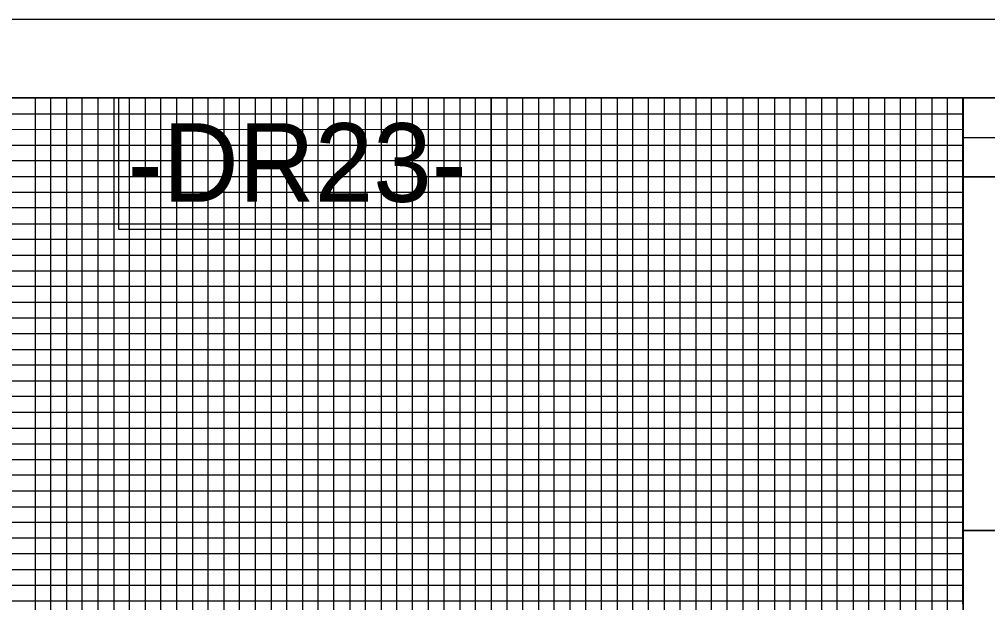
# Model space of a CAD drawing. Extents: x 505602 to 527661, y 418813 to 494436.
# Drawn here: x 506769.1 to 507076.9, y 484023.2 to 484208.7 of the extents above; entities that cross this region are included whole.
import ezdxf

# ---------------------------------------------------------------- set-up
doc = ezdxf.new("R2010")
doc.units = 0
for name, color, linetype in [('Old_Level_1', 7, 'Continuous'), ('Prop Grid Mask', 7, 'Continuous'), ('Sheet Layout Profile Border Port 2', 7, 'Continuous'), ('Sheet Plot Border Outside CELL', 7, 'Continuous'), ('Sheet Profile CELL', 7, 'Continuous'), ('Sheet Profile Grid Major CELL', 7, 'Continuous'), ('Sheet Profile Grid Middle CELL', 7, 'Continuous'), ('Sheet Profile Grid Minor CELL', 7, 'Continuous'), ('Sheet Sticker Exception Certification CELL', 7, 'Continuous')]:
    doc.layers.add(name, color=color, linetype=linetype)

msp = doc.modelspace()

# ---------------------------------------------------------------- linework, layer by layer
at = {"layer": 'Prop Grid Mask'}
msp.add_lwpolyline([(506919.08, 484183.71), (506800.61, 484183.71), (506800.61, 484142), (506919.08, 484142)], close=True, dxfattribs=at)
at = {"layer": 'Sheet Layout Profile Border Port 2'}
msp.add_lwpolyline([(506719.08, 484183.71), (507069.08, 484183.71), (507069.08, 483683.71), (506719.08, 483683.71)], close=True, dxfattribs=at)
at = {"layer": 'Sheet Plot Border Outside CELL'}
msp.add_lwpolyline([(505602.08, 483108.71), (507286.08, 483108.71), (507286.08, 484208.71), (505602.08, 484208.71)], close=True, dxfattribs=at)
at = {"layer": 'Sheet Profile CELL'}
msp.add_line((507069.03, 484171.16), (507269.08, 484171.16), dxfattribs=at)
for points in [[(507269.08, 484183.71), (505769.08, 484183.71), (505769.08, 483133.71), (507269.08, 483133.71)], [(507069.03, 484183.71), (507269.08, 484183.71), (507269.08, 484158.66), (507069.03, 484158.66)], [(507069.03, 484158.66), (507169.08, 484158.66), (507169.08, 484046.16), (507069.03, 484046.16)]]:
    msp.add_lwpolyline(points, close=True, dxfattribs=at)
at = {"layer": 'Sheet Profile Grid Major CELL'}
for points in [[(506769.08, 484183.71), (506819.08, 484183.71), (506819.08, 483683.71), (506869.08, 483683.71), (506869.08, 484183.71), (506919.08, 484183.71), (506919.08, 483683.71), (506969.08, 483683.71), (506969.08, 484183.71), (507019.08, 484183.71), (507019.08, 483683.71), (507069.08, 483683.71), (507069.08, 484183.71), (507095.38, 484183.71)], [(505769.08, 484133.71), (507069.08, 484133.71)], [(507069.08, 484083.71), (505769.08, 484083.71), (505769.08, 484033.71), (507069.08, 484033.71)]]:
    msp.add_lwpolyline(points, dxfattribs=at)
at = {"layer": 'Sheet Profile Grid Middle CELL'}
msp.add_line((505769.08, 484158.71), (507069.03, 484158.71), dxfattribs=at)
msp.add_line((505769.08, 484158.71), (507069.03, 484158.71), dxfattribs=at)
for points in [[(506744.08, 483683.71), (506794.08, 483683.71), (506794.08, 484183.71), (506844.08, 484183.71), (506844.08, 483683.71), (506894.08, 483683.71), (506894.08, 484183.71), (506944.08, 484183.71), (506944.08, 483683.71), (506994.08, 483683.71), (506994.08, 484183.71), (507044.08, 484183.71), (507044.08, 483683.71), (507094.08, 483683.71), (507094.08, 484022.66)], [(507069.08, 484108.71), (505769.08, 484108.71), (505769.08, 484058.71), (507069.08, 484058.71)]]:
    msp.add_lwpolyline(points, dxfattribs=at)
at = {"layer": 'Sheet Profile Grid Minor CELL'}
for p, q in [((505819.08, 484178.71), (507069.08, 484178.71)), ((507069.08, 484173.71), (505819.08, 484173.36)), ((505819.08, 484168.71), (507069.08, 484168.71)), ((507069.03, 484048.71), (505819.08, 484048.71)), ((507069.08, 484043.71), (505819.08, 484043.71)), ((507069.08, 484038.71), (505819.08, 484038.71)), ((505819.08, 484028.71), (507069.08, 484028.71)), ((507069.08, 484023.71), (505819.08, 484023.71))]:
    msp.add_line(p, q, dxfattribs=at)
for points in [[(506764.08, 484183.71), (506774.08, 484183.71), (506774.08, 483683.71)], [(506779.08, 483683.71), (506779.08, 484183.71), (506784.08, 484183.71), (506784.08, 483683.71)], [(506789.08, 483683.71), (506789.08, 484183.71), (506799.08, 484183.71), (506799.08, 483683.71)], [(506804.08, 483683.71), (506804.08, 484183.71), (506809.08, 484183.71), (506809.08, 483683.71)], [(506814.08, 483683.71), (506814.08, 484183.71), (506824.08, 484183.71), (506824.08, 483683.71)], [(506829.08, 483683.71), (506829.08, 484183.71), (506834.08, 484183.71), (506834.08, 483683.71)], [(506839.08, 483683.71), (506839.08, 484183.71), (506849.08, 484183.71), (506849.08, 483683.71)], [(506854.08, 483683.71), (506854.08, 484183.71), (506859.08, 484183.71), (506859.08, 483683.71)], [(506864.08, 483683.71), (506864.08, 484183.71), (506874.08, 484183.71), (506874.08, 483683.71)], [(506879.08, 483683.71), (506879.08, 484183.71), (506884.08, 484183.71), (506884.08, 483683.71)], [(506889.08, 483683.71), (506889.08, 484183.71), (506899.08, 484183.71), (506899.08, 483683.71)], [(506904.08, 483683.71), (506904.08, 484183.71), (506909.08, 484183.71), (506909.08, 483683.71)], [(506914.08, 483683.71), (506914.08, 484183.71), (506924.08, 484183.71), (506924.08, 483683.71)], [(506929.08, 483683.71), (506929.08, 484183.71), (506934.08, 484183.71), (506934.08, 483683.71)], [(506939.08, 483683.71), (506939.08, 484183.71), (506949.08, 484183.71), (506949.08, 483683.71)], [(506954.08, 483683.71), (506954.08, 484183.71), (506959.08, 484183.71), (506959.08, 483683.71)], [(506964.08, 483683.71), (506964.08, 484183.71), (506974.08, 484183.71), (506974.08, 483683.71)], [(506979.08, 483683.71), (506979.08, 484183.71), (506984.08, 484183.71), (506984.08, 483683.71)], [(506989.08, 483683.71), (506989.08, 484183.71), (506999.08, 484183.71), (506999.08, 483683.71)], [(507004.08, 483683.71), (507004.08, 484183.71), (507009.08, 484183.71), (507009.08, 483683.71)], [(507014.08, 483683.71), (507014.08, 484183.71), (507024.08, 484183.71), (507024.08, 483683.71)], [(507029.08, 483683.71), (507029.08, 484183.71), (507034.08, 484183.71), (507034.08, 483683.71)], [(507039.08, 483683.71), (507039.08, 484183.71), (507049.08, 484183.71), (507049.08, 483683.71)], [(507054.08, 483683.71), (507054.08, 484183.71), (507059.08, 484183.71), (507059.08, 483683.71)], [(507064.08, 483683.71), (507064.08, 484183.71), (507074.08, 484183.71)], [(507069.08, 484163.71), (505819.08, 484163.71), (505819.08, 484153.71), (507069.08, 484153.71)], [(507069.03, 484148.71), (505819.08, 484148.71), (505819.08, 484143.71), (507069.08, 484143.71)], [(507069.08, 484138.71), (505819.08, 484138.71), (505819.08, 484128.71), (507069.08, 484128.71)], [(507069.08, 484123.71), (505819.08, 484123.71), (505819.08, 484118.71), (507069.08, 484118.71)], [(507069.08, 484113.71), (505819.08, 484113.71), (505819.08, 484103.71), (507069.08, 484103.71)], [(507069.08, 484098.71), (505819.08, 484098.71), (505819.08, 484093.71), (507069.08, 484093.71)], [(507069.08, 484088.71), (505819.08, 484088.71), (505819.08, 484078.71), (507069.08, 484078.71)], [(507069.08, 484073.61), (505819.18, 484073.61), (505819.18, 484068.71), (507069.08, 484068.71)], [(507069.08, 484063.71), (505819.08, 484063.71), (505819.08, 484053.71), (507069.08, 484053.71)]]:
    msp.add_lwpolyline(points, dxfattribs=at)
at = {"layer": 'Sheet Sticker Exception Certification CELL'}
for p, q in [((507069.03, 484022.66), (507069.03, 484046.16)), ((507069.03, 484046.16), (507269.07, 484046.16)), ((507069.03, 484022.66), (507069.03, 484046.16)), ((507069.03, 484046.16), (507269.07, 484046.16))]:
    msp.add_line(p, q, dxfattribs=at)

# ---------------------------------------------------------------- texts
at = {"layer": 'Old_Level_1'}
msp.add_text('-DR23-', height=25, dxfattribs=at).set_placement((506803.53, 484150.68))

doc.saveas('drawing.dxf')
